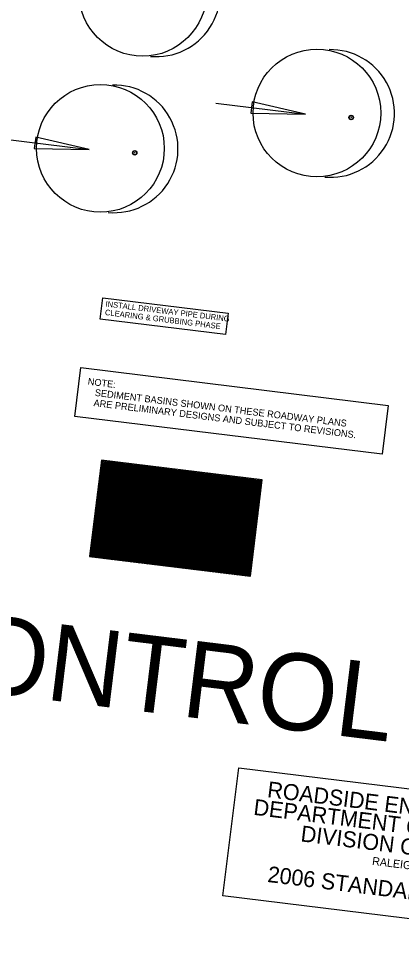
# Model space of a CAD drawing. Extents: x 2470000 to 2520000, y 340000 to 380000.
# Drawn here: x 2482116 to 2482450, y 372573 to 373379 of the extents above; entities that cross this region are included whole.
import ezdxf

# ---------------------------------------------------------------- set-up
doc = ezdxf.new("R2010")
doc.units = 0
for name, color, linetype in [('Default', 7, 'Continuous'), ('Erosion Control Plan Text CELL', 7, 'Continuous'), ('ESA Border CG', 7, 'Continuous'), ('ESA Hatching CG', 7, 'Continuous'), ('Install Driveway Pipe During Clearing and Grubbing Phase CG CELL', 7, 'Continuous'), ('Riser Basin Both CELL', 7, 'Continuous'), ('Riser Basin CG CELL', 7, 'Continuous'), ('Riser Basin Final CELL', 7, 'Continuous'), ('Temporary Basin Design for Field Inspection Plans Note Both CELL', 7, 'Continuous')]:
    doc.layers.add(name, color=color, linetype=linetype)

msp = doc.modelspace()

# ---------------------------------------------------------------- linework, layer by layer
at = {"layer": 'Default'}
msp.add_lwpolyline([(2482308.27, 372723.72), (2482625.53, 372684.72), (2482611.78, 372572.9), (2482294.52, 372611.9)], close=True, dxfattribs=at)
at = {"layer": 'ESA Border CG'}
msp.add_lwpolyline([(2482178.09, 372908.41), (2482318.44, 372891.16), (2482328.79, 372975.37), (2482188.44, 372992.62)], close=True, dxfattribs=at)
at = {"layer": 'ESA Hatching CG'}
for p, q in [((2482184.13, 372957.54), (2482223.52, 372988.31)), ((2482184.3, 372958.94), (2482222.12, 372988.48)), ((2482184.47, 372960.35), (2482220.71, 372988.65)), ((2482184.64, 372961.75), (2482219.31, 372988.83)), ((2482184.82, 372963.16), (2482217.91, 372989)), ((2482184.99, 372964.56), (2482216.5, 372989.17)), ((2482185.16, 372965.96), (2482215.1, 372989.34)), ((2482185.33, 372967.37), (2482213.69, 372989.52)), ((2482185.51, 372968.77), (2482212.29, 372989.69)), ((2482185.68, 372970.17), (2482210.89, 372989.86)), ((2482185.85, 372971.58), (2482209.48, 372990.04)), ((2482186.02, 372972.98), (2482208.08, 372990.21)), ((2482186.2, 372974.38), (2482206.68, 372990.38)), ((2482186.37, 372975.79), (2482205.27, 372990.55)), ((2482186.54, 372977.19), (2482203.87, 372990.73)), ((2482186.71, 372978.6), (2482202.47, 372990.9)), ((2482186.89, 372980), (2482201.06, 372991.07)), ((2482187.06, 372981.4), (2482199.66, 372991.24)), ((2482187.23, 372982.81), (2482198.25, 372991.42)), ((2482187.4, 372984.21), (2482196.85, 372991.59)), ((2482187.58, 372985.61), (2482195.45, 372991.76)), ((2482187.75, 372987.02), (2482194.04, 372991.93)), ((2482187.92, 372988.42), (2482192.64, 372992.11)), ((2482188.1, 372989.82), (2482191.24, 372992.28)), ((2482188.27, 372991.23), (2482189.83, 372992.45)), ((2482178.09, 372908.41), (2482272.65, 372982.27)), ((2482178.26, 372909.82), (2482271.24, 372982.44)), ((2482178.43, 372911.22), (2482269.84, 372982.62)), ((2482178.61, 372912.62), (2482268.44, 372982.79)), ((2482178.78, 372914.03), (2482267.03, 372982.96)), ((2482178.95, 372915.43), (2482265.63, 372983.13)), ((2482179.12, 372916.83), (2482264.23, 372983.31)), ((2482179.3, 372918.24), (2482262.82, 372983.48)), ((2482179.47, 372919.64), (2482261.42, 372983.65)), ((2482179.49, 372908.24), (2482274.05, 372982.1)), ((2482179.64, 372921.05), (2482260.02, 372983.82)), ((2482179.81, 372922.45), (2482258.61, 372984)), ((2482179.99, 372923.85), (2482257.21, 372984.17)), ((2482180.16, 372925.26), (2482255.8, 372984.34)), ((2482180.33, 372926.66), (2482254.4, 372984.51)), ((2482180.5, 372928.06), (2482253, 372984.69)), ((2482180.68, 372929.47), (2482251.59, 372984.86)), ((2482180.85, 372930.87), (2482250.19, 372985.03)), ((2482180.89, 372908.06), (2482275.46, 372981.93)), ((2482181.02, 372932.27), (2482248.79, 372985.2)), ((2482181.19, 372933.68), (2482247.38, 372985.38)), ((2482181.37, 372935.08), (2482245.98, 372985.55)), ((2482181.54, 372936.49), (2482244.58, 372985.72)), ((2482181.71, 372937.89), (2482243.17, 372985.89)), ((2482181.88, 372939.29), (2482241.77, 372986.07)), ((2482182.06, 372940.7), (2482240.36, 372986.24)), ((2482182.23, 372942.1), (2482238.96, 372986.41)), ((2482182.29, 372907.89), (2482276.86, 372981.75)), ((2482182.4, 372943.5), (2482237.56, 372986.58)), ((2482182.57, 372944.91), (2482236.15, 372986.76)), ((2482182.75, 372946.31), (2482234.75, 372986.93)), ((2482182.92, 372947.71), (2482233.35, 372987.1)), ((2482183.09, 372949.12), (2482231.94, 372987.27)), ((2482183.26, 372950.52), (2482230.54, 372987.45)), ((2482183.44, 372951.93), (2482229.14, 372987.62)), ((2482183.61, 372953.33), (2482227.73, 372987.79)), ((2482183.7, 372907.72), (2482278.26, 372981.58)), ((2482183.78, 372954.73), (2482226.33, 372987.96)), ((2482183.95, 372956.14), (2482224.92, 372988.14)), ((2482185.1, 372907.55), (2482279.67, 372981.41)), ((2482186.51, 372907.37), (2482281.07, 372981.24)), ((2482187.91, 372907.2), (2482282.47, 372981.06)), ((2482189.31, 372907.03), (2482283.88, 372980.89)), ((2482190.72, 372906.86), (2482285.28, 372980.72)), ((2482192.12, 372906.68), (2482286.68, 372980.55)), ((2482193.52, 372906.51), (2482288.09, 372980.37)), ((2482194.93, 372906.34), (2482289.49, 372980.2)), ((2482196.33, 372906.17), (2482290.9, 372980.03)), ((2482197.73, 372905.99), (2482292.3, 372979.86)), ((2482199.14, 372905.82), (2482293.7, 372979.68)), ((2482200.54, 372905.65), (2482295.11, 372979.51)), ((2482201.95, 372905.48), (2482296.51, 372979.34)), ((2482203.35, 372905.3), (2482297.91, 372979.16)), ((2482204.75, 372905.13), (2482299.32, 372978.99)), ((2482206.16, 372904.96), (2482300.72, 372978.82)), ((2482207.56, 372904.79), (2482302.12, 372978.65)), ((2482208.96, 372904.61), (2482303.53, 372978.47)), ((2482210.37, 372904.44), (2482304.93, 372978.3)), ((2482211.77, 372904.27), (2482306.34, 372978.13)), ((2482213.17, 372904.1), (2482307.74, 372977.96)), ((2482214.58, 372903.92), (2482309.14, 372977.78)), ((2482215.98, 372903.75), (2482310.55, 372977.61)), ((2482217.39, 372903.58), (2482311.95, 372977.44)), ((2482218.79, 372903.41), (2482313.35, 372977.27)), ((2482220.19, 372903.23), (2482314.76, 372977.09)), ((2482221.6, 372903.06), (2482316.16, 372976.92)), ((2482223, 372902.89), (2482317.56, 372976.75)), ((2482224.4, 372902.72), (2482318.97, 372976.58)), ((2482225.81, 372902.54), (2482320.37, 372976.4)), ((2482227.21, 372902.37), (2482321.78, 372976.23)), ((2482228.61, 372902.2), (2482323.18, 372976.06)), ((2482230.02, 372902.03), (2482324.58, 372975.89)), ((2482231.42, 372901.85), (2482325.99, 372975.71)), ((2482232.83, 372901.68), (2482327.39, 372975.54)), ((2482234.23, 372901.51), (2482328.79, 372975.37)), ((2482235.63, 372901.34), (2482328.62, 372973.96)), ((2482237.04, 372901.16), (2482328.45, 372972.56)), ((2482238.44, 372900.99), (2482328.28, 372971.16)), ((2482239.84, 372900.82), (2482328.1, 372969.75)), ((2482241.25, 372900.65), (2482327.93, 372968.35)), ((2482242.65, 372900.47), (2482327.76, 372966.95)), ((2482244.06, 372900.3), (2482327.59, 372965.54)), ((2482245.46, 372900.13), (2482327.41, 372964.14)), ((2482246.86, 372899.95), (2482327.24, 372962.74)), ((2482248.27, 372899.78), (2482327.07, 372961.33)), ((2482249.67, 372899.61), (2482326.9, 372959.93)), ((2482251.07, 372899.44), (2482326.72, 372958.52)), ((2482252.48, 372899.26), (2482326.55, 372957.12)), ((2482253.88, 372899.09), (2482326.38, 372955.72)), ((2482255.28, 372898.92), (2482326.21, 372954.31)), ((2482256.69, 372898.75), (2482326.03, 372952.91)), ((2482258.09, 372898.57), (2482325.86, 372951.51)), ((2482259.5, 372898.4), (2482325.69, 372950.1)), ((2482260.9, 372898.23), (2482325.52, 372948.7)), ((2482262.3, 372898.06), (2482325.34, 372947.3)), ((2482263.71, 372897.88), (2482325.17, 372945.89)), ((2482265.11, 372897.71), (2482325, 372944.49)), ((2482266.51, 372897.54), (2482324.83, 372943.08)), ((2482267.92, 372897.37), (2482324.65, 372941.68)), ((2482269.32, 372897.19), (2482324.48, 372940.28)), ((2482270.72, 372897.02), (2482324.31, 372938.87)), ((2482272.13, 372896.85), (2482324.14, 372937.47)), ((2482273.53, 372896.68), (2482323.96, 372936.07)), ((2482274.94, 372896.5), (2482323.79, 372934.66)), ((2482276.34, 372896.33), (2482323.62, 372933.26)), ((2482277.74, 372896.16), (2482323.44, 372931.86)), ((2482279.15, 372895.99), (2482323.27, 372930.45)), ((2482280.55, 372895.81), (2482323.1, 372929.05)), ((2482281.95, 372895.64), (2482322.93, 372927.64)), ((2482283.36, 372895.47), (2482322.75, 372926.24)), ((2482284.76, 372895.3), (2482322.58, 372924.84)), ((2482286.16, 372895.12), (2482322.41, 372923.43)), ((2482287.57, 372894.95), (2482322.24, 372922.03)), ((2482288.97, 372894.78), (2482322.06, 372920.63)), ((2482290.38, 372894.61), (2482321.89, 372919.22)), ((2482291.78, 372894.43), (2482321.72, 372917.82)), ((2482293.18, 372894.26), (2482321.55, 372916.42)), ((2482294.59, 372894.09), (2482321.37, 372915.01)), ((2482295.99, 372893.92), (2482321.2, 372913.61)), ((2482297.39, 372893.74), (2482321.03, 372912.2)), ((2482298.8, 372893.57), (2482320.86, 372910.8)), ((2482300.2, 372893.4), (2482320.68, 372909.4)), ((2482301.6, 372893.23), (2482320.51, 372907.99)), ((2482303.01, 372893.05), (2482320.34, 372906.59)), ((2482304.41, 372892.88), (2482320.17, 372905.19)), ((2482305.82, 372892.71), (2482319.99, 372903.78)), ((2482307.22, 372892.54), (2482319.82, 372902.38)), ((2482308.62, 372892.36), (2482319.65, 372900.98)), ((2482310.03, 372892.19), (2482319.48, 372899.57)), ((2482311.43, 372892.02), (2482319.3, 372898.17)), ((2482312.83, 372891.85), (2482319.13, 372896.76)), ((2482314.24, 372891.67), (2482318.96, 372895.36)), ((2482315.64, 372891.5), (2482318.79, 372893.96)), ((2482317.04, 372891.33), (2482318.61, 372892.55))]:
    msp.add_line(p, q, dxfattribs=at)
at = {"layer": 'Install Driveway Pipe During Clearing and Grubbing Phase CG CELL'}
msp.add_lwpolyline([(2482189.61, 373134.57), (2482299.01, 373121.12), (2482296.72, 373102.47), (2482187.32, 373115.92)], close=True, dxfattribs=at)
at = {"layer": 'Riser Basin Both CELL'}
for p, q in [((2482099.28, 373273.73), (2482177.66, 373264.1)), ((2482131, 373274.96), (2482129.75, 373264.82)), ((2482177.66, 373264.1), (2482131, 373274.96)), ((2482129.75, 373264.82), (2482177.66, 373264.1))]:
    msp.add_line(p, q, dxfattribs=at)
for centre, radius in [((2482187.55, 373265.07), 55.78), ((2482217.49, 373261.15), 1.92), ((2482217.49, 373261.15), 1.91), ((2482217.48, 373261.15), 1.89), ((2482217.48, 373261.15), 1.87), ((2482217.48, 373261.15), 1.85), ((2482217.48, 373261.15), 1.83), ((2482217.48, 373261.15), 1.81), ((2482217.48, 373261.15), 1.8), ((2482217.48, 373261.15), 1.78), ((2482217.48, 373261.15), 1.76), ((2482217.48, 373261.15), 1.74), ((2482217.48, 373261.15), 1.72), ((2482217.48, 373261.15), 1.71), ((2482217.48, 373261.15), 1.69), ((2482217.48, 373261.15), 1.67), ((2482217.47, 373261.15), 1.66), ((2482217.47, 373261.15), 1.64), ((2482217.47, 373261.15), 1.63), ((2482217.35, 373261.16), 0.163), ((2482217.48, 373261.21), 0.163), ((2482217.34, 373261.17), 0.0163), ((2482217.39, 373261.1), 0.00163), ((2482217.48, 373261.22), 0.0163)]:
    msp.add_circle(centre, radius, dxfattribs=at)
msp.add_arc((2482199.5, 373264.66), 55.78, 264.72356, 91.40886, dxfattribs=at)
at = {"layer": 'Riser Basin CG CELL'}
msp.add_circle((2482224.44, 373401.37), 55.78, dxfattribs=at)
msp.add_arc((2482236.39, 373400.97), 55.78, 264.72356, 91.40886, dxfattribs=at)
at = {"layer": 'Riser Basin Final CELL'}
for p, q in [((2482288.3, 373304.64), (2482366.67, 373295)), ((2482320.01, 373305.86), (2482318.77, 373295.73)), ((2482366.67, 373295), (2482320.01, 373305.86)), ((2482318.77, 373295.73), (2482366.67, 373295))]:
    msp.add_line(p, q, dxfattribs=at)
for centre, radius in [((2482376.57, 373295.97), 55.78), ((2482406.5, 373292.05), 1.92), ((2482406.5, 373292.05), 1.91), ((2482406.5, 373292.05), 1.89), ((2482406.5, 373292.05), 1.87), ((2482406.5, 373292.05), 1.85), ((2482406.5, 373292.05), 1.83), ((2482406.5, 373292.06), 1.81), ((2482406.5, 373292.06), 1.8), ((2482406.5, 373292.06), 1.78), ((2482406.5, 373292.06), 1.76), ((2482406.5, 373292.06), 1.74), ((2482406.5, 373292.06), 1.72), ((2482406.49, 373292.06), 1.71), ((2482406.49, 373292.06), 1.69), ((2482406.49, 373292.06), 1.67), ((2482406.49, 373292.06), 1.66), ((2482406.49, 373292.06), 1.64), ((2482406.49, 373292.06), 1.63), ((2482406.37, 373292.07), 0.163), ((2482406.5, 373292.12), 0.163), ((2482406.36, 373292.07), 0.0163), ((2482406.41, 373292), 0.00163), ((2482406.5, 373292.12), 0.0163)]:
    msp.add_circle(centre, radius, dxfattribs=at)
msp.add_arc((2482388.51, 373295.57), 55.78, 264.72356, 91.40886, dxfattribs=at)
at = {"layer": 'Temporary Basin Design for Field Inspection Plans Note Both CELL'}
msp.add_lwpolyline([(2482170.39, 373073.49), (2482438.82, 373040.5), (2482433.57, 372997.77), (2482165.14, 373030.76)], close=True, dxfattribs=at)

# ---------------------------------------------------------------- texts
at = {"layer": 'Default'}
for s, height, p in [('ROADSIDE ENVIRONMENTAL UNIT', 13.9888, (2482332.71, 372698.21)), ('DEPARTMENT OF TRANSPORTATION', 13.9888, (2482320.7, 372682.83)), ('DIVISION OF HIGHWAYS', 13.9888, (2482361.89, 372659.63)), ('RALEIGH, N.C.', 6.9944, (2482424.52, 372639.12)), ('2006 STANDARD SPECIFICATIONS', 13.9937, (2482332.97, 372624.15))]:
    msp.add_text(s, height=height, rotation=352.99213, dxfattribs=at).set_placement(p)
at = {"layer": 'Erosion Control Plan Text CELL'}
msp.add_text('EROSION CONTROL PLAN', height=67.0536, rotation=352.99213, dxfattribs=at).set_placement((2481569.67, 372853.5))
at = {"layer": 'Install Driveway Pipe During Clearing and Grubbing Phase CG CELL'}
for s, p in [('INSTALL DRIVEWAY PIPE DURING', (2482191.73, 373126.92)), ('CLEARING & GRUBBING PHASE', (2482191.28, 373119.48))]:
    msp.add_text(s, height=4.9621, rotation=352.99213, dxfattribs=at).set_placement(p)
at = {"layer": 'Temporary Basin Design for Field Inspection Plans Note Both CELL'}
for s, p in [('NOTE:  ', (2482176.23, 373058.67)), ('     SEDIMENT BASINS SHOWN ON THESE ROADWAY PLANS', (2482171.3, 373050.21)), ('     ARE PRELIMINARY DESIGNS AND SUBJECT TO REVISIONS.', (2482170.22, 373041.27))]:
    msp.add_text(s, height=6, rotation=352.99213, dxfattribs=at).set_placement(p)

doc.saveas('drawing.dxf')
